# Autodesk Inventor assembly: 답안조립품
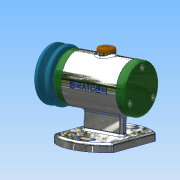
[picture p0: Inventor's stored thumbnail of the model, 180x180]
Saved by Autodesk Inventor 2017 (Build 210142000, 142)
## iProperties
Part Number: 답안조립품
Material: 일반
Document SubType Name: Assembly
Designer: user
Author: user
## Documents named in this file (14)
- C:\Users\user\Desktop\710906V1027\답안조립품.iam
- C:\Users\user\Desktop\710906V1027\본체.ipt
- C:\Users\user\Desktop\710906V1027\V벨트풀리.ipt
- C:\Users\user\Desktop\710906V1027\너트 M8.ipt
- C:\Users\user\Desktop\710906V1027\뒤커버.ipt
- C:\Users\user\Desktop\710906V1027\베어링 15x32x9.ipt
- C:\Users\user\Desktop\710906V1027\볼트 M4x12.ipt
- C:\Users\user\Desktop\710906V1027\스프링와셔 8.ipt
- C:\Users\user\Desktop\710906V1027\앞커버.ipt
- C:\Users\user\Desktop\710906V1027\오일 실 15x25x7.ipt
- C:\Users\user\Desktop\710906V1027\와셔 8x17.ipt
- C:\Users\user\Desktop\710906V1027\축.ipt
- C:\Users\user\Desktop\710906V1027\캡.ipt
- C:\Users\user\Desktop\710906V1027\키 3x3.ipt
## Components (1 placed, 1 different names)
1. V벨트풀리:1
